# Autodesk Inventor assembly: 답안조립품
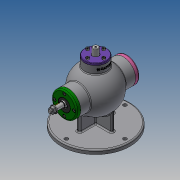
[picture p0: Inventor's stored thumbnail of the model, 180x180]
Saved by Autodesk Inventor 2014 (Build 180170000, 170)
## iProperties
Created: 2020-08
Part Number: 답안조립품
Document SubType Name: Assembly
Designer: kb542-5
Author: kb542-5
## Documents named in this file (18)
- C:\Users\kb542-5\Desktop\700806V1003\답안조립품.iam
- C:\Users\kb542-5\Desktop\700806V1003\본체.ipt
- C:\Users\kb542-5\Desktop\700806V1003\편심축.ipt
- C:\Users\kb542-5\Desktop\700806V1003\칼라.ipt
- C:\Users\kb542-5\Desktop\700806V1003\오일 실 15 30 7.ipt
- C:\Users\kb542-5\Desktop\700806V1003\앞커버.ipt
- C:\Users\kb542-5\Desktop\700806V1003\슬라이드.ipt
- C:\Users\kb542-5\Desktop\700806V1003\상부커버.ipt
- C:\Users\kb542-5\Desktop\700806V1003\볼트 M4.ipt
- C:\Users\kb542-5\Desktop\700806V1003\베어링 6202.ipt
- 베어링 6202.ipt
- C:\Users\kb542-5\Desktop\700806V1003\멈춤링 35x1.6.ipt
- 멈춤링 35x1.6.ipt
- C:\Users\kb542-5\Desktop\700806V1003\멈춤링 15x1.ipt
- C:\Users\kb542-5\Desktop\700806V1003\뒤커버.ipt
- C:\Users\kb542-5\Desktop\700806V1003\너트 M8.ipt
- C:\Users\kb542-5\Desktop\700806V1003\V-벨트풀리.ipt
- C:\Users\kb542-5\Desktop\700806V1003\Ű 3x3x12.ipt
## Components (2 placed, 2 different names)
1. V-벨트풀리:1
2. Ű 3x3x12:1
